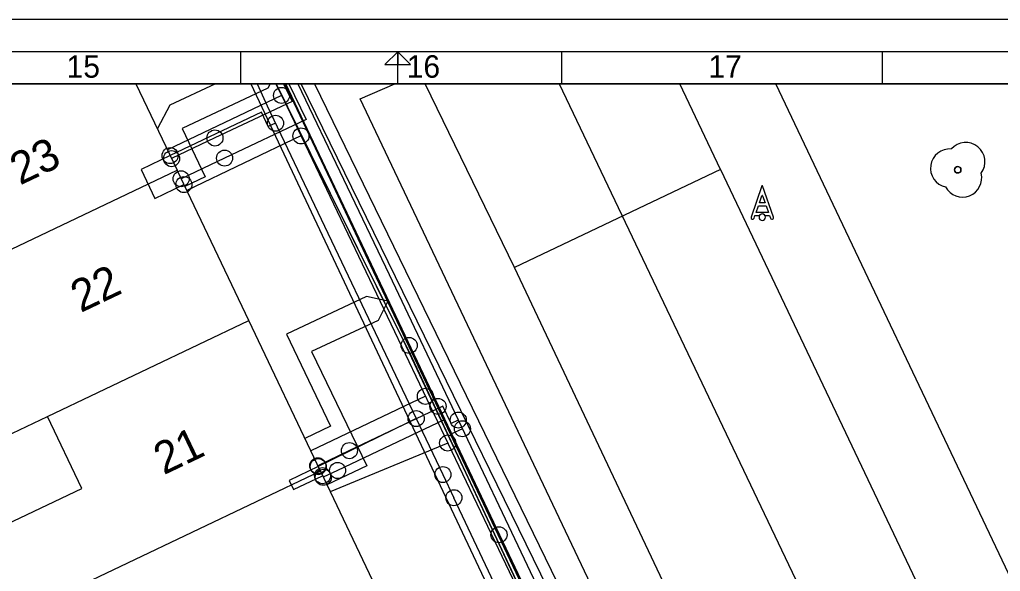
# Model space of a CAD drawing. Extents: x 192672 to 192910, y 446344 to 446512.
# Drawn here: x 192813.76 to 192844.33, y 446494.56 to 446511.76 of the extents above; entities that cross this region are included whole.
import ezdxf

# ---------------------------------------------------------------- set-up
doc = ezdxf.new("R2010")
doc.units = 0
for name, color, linetype in [('1010 viewport', 7, 'Continuous'), ('B-OI-KL-()_PUNTVANLEVERING_WATER-S', 7, 'Continuous'), ('B-OI-KL-BUISLEIDING_OLIEGASCHEMICALIEN_GASLAGEDRUK-G', 7, 'Continuous'), ('B-OI-KL-DATA-G', 7, 'Continuous'), ('B-OI-KL-DATA_KABELBED-G', 7, 'Continuous'), ('B-OI-KL-DATA_OVERIG-S', 7, 'Continuous'), ('B-OI-KL-ET_LS-G', 7, 'Continuous'), ('B-OI-KL-ET_LS_DELIVERYPOINT-S', 7, 'Continuous'), ('B-OI-KL-ET_LS_MOF-S', 7, 'Continuous'), ('B-OI-KL-GAS_LD_AFTAKZADEL-S', 7, 'Continuous'), ('B-OI-KL-GAS_LD_DELIVERYPOINT-S', 7, 'Continuous'), ('B-OI-KL-GAS_LD_OVERGANGSSTUK-S', 7, 'Continuous'), ('B-OI-KL-WATER-G', 7, 'Continuous'), ('B-OI-RI-RIOOLVRIJVERVAL-G', 7, 'Continuous'), ('boom', 7, 'Continuous'), ('bovenleidingmast', 7, 'Continuous'), ('Default', 7, 'Continuous'), ('huisnummerreeks BGT', 7, 'Continuous'), ('kant open verharding', 7, 'Continuous'), ('kant verharding', 7, 'Continuous'), ('pand op maaiveld vlak', 7, 'Continuous'), ('X-XX-AL-TEKENBLAD-S', 7, 'Continuous')]:
    doc.layers.add(name, color=color, linetype=linetype)

# ---------------------------------------------------------------- blocks, each defined once
blk = doc.blocks.new('B-OI-KL-GAS_LD_AFTAKZADEL-S')
at = {"layer": 'Default'}
blk.add_circle((0, 0), 0.25, dxfattribs=at)
blk = doc.blocks.new('B-OI-KL-GAS_LD_DELIVERYPOINT-S')
at = {"layer": 'Default'}
blk.add_circle((0, 0), 0.25, dxfattribs=at)
blk = doc.blocks.new('B-OI-KL-GAS_LD_OVERGANGSSTUK-S')
at = {"layer": 'Default'}
blk.add_circle((0, 0), 0.25, dxfattribs=at)
blk = doc.blocks.new('B-OI-KL-ET_LS_DELIVERYPOINT-S')
at = {"layer": 'Default'}
blk.add_circle((0, 0), 0.25, dxfattribs=at)
blk = doc.blocks.new('B-OI-KL-ET_LS_MOF-S')
at = {"layer": 'Default'}
blk.add_circle((0, 0), 0.25, dxfattribs=at)
blk = doc.blocks.new('B-OI-KL-DATA_OVERIG-S')
at = {"layer": 'Default'}
blk.add_circle((0, 0), 0.25, dxfattribs=at)
blk = doc.blocks.new('B-OI-KL-()_PUNTVANLEVERING_WATER-S')
at = {"layer": 'Default'}
blk.add_circle((0, 0), 0.25, dxfattribs=at)

msp = doc.modelspace()

# ---------------------------------------------------------------- linework, layer by layer
at = {"layer": '1010 viewport'}
msp.add_lwpolyline([(192675.743, 446509.756), (192860.643, 446509.756), (192860.643, 446345.556), (192675.743, 446345.556)], close=True, dxfattribs=at)
at = {"layer": 'B-OI-KL-BUISLEIDING_OLIEGASCHEMICALIEN_GASLAGEDRUK-G'}
for points in [[(192821.989, 446509.756), (192822.251, 446509.208), (192819.848, 446508.066)], [(192822.155, 446509.756), (192822.687, 446508.645), (192820.149, 446507.439)], [(192822.433, 446509.756), (192825.279, 446503.813), (192831.728, 446490.219), (192841.146, 446471.04), (192848.608, 446455.57), (192845.591, 446448.244), (192845.453, 446447.8)], [(192819.848, 446508.066), (192818.496, 446507.422)], [(192820.149, 446507.439), (192818.795, 446506.794)], [(192827.432, 446499.275), (192827.206, 446499.168), (192826.951, 446499.706), (192824.039, 446498.321)], [(192827.561, 446499.003), (192827.199, 446498.832), (192826.987, 446499.28), (192823.669, 446497.702)], [(192824.039, 446498.321), (192823.054, 446497.852)], [(192823.669, 446497.702), (192823.225, 446497.491)]]:
    msp.add_lwpolyline(points, dxfattribs=at)
at = {"layer": 'B-OI-KL-DATA-G'}
for q in [(192825.713, 446501.766), (192823.186, 446506.85)]:
    msp.add_line((192821.742, 446509.756), q, dxfattribs=at)
for points in [[(192819.864, 446509.756), (192818.447, 446509.084), (192818.053, 446508.359)], [(192821.572, 446509.756), (192821.501, 446509.616), (192818.831, 446508.364), (192819.548, 446506.856), (192818.913, 446506.553)], [(192821.742, 446509.756), (192825.984, 446501.22), (192835.895, 446480.007), (192842.472, 446466.378), (192848.635, 446454.503), (192848.764, 446454.232), (192845.185, 446446.654), (192842.489, 446440.231), (192836.203, 446423.068)], [(192821.742, 446509.756), (192825.984, 446501.22), (192835.895, 446480.007), (192842.472, 446466.378), (192848.635, 446454.503), (192848.764, 446454.232), (192845.185, 446446.654), (192842.489, 446440.231), (192836.203, 446423.068), (192839.811, 446421.866), (192851.515, 446418.004), (192854.977, 446417.712)], [(192821.742, 446509.756), (192825.984, 446501.22), (192835.895, 446480.007), (192842.472, 446466.378), (192842.564, 446466.201), (192838.77, 446464.389), (192838.682, 446464.573)], [(192821.742, 446509.756), (192825.984, 446501.22), (192835.895, 446480.007), (192838.867, 446473.848)], [(192821.742, 446509.756), (192825.984, 446501.22), (192835.895, 446480.007), (192836.607, 446478.531)], [(192821.742, 446509.756), (192825.984, 446501.22), (192834.713, 446482.538)], [(192821.742, 446509.756), (192825.984, 446501.22), (192832.292, 446487.72)], [(192821.742, 446509.756), (192825.984, 446501.22), (192830.072, 446492.472)], [(192821.742, 446509.756), (192825.984, 446501.22), (192828.007, 446496.891)], [(192821.742, 446509.756), (192825.984, 446501.22), (192835.895, 446480.007), (192842.472, 446466.378), (192848.635, 446454.503), (192848.764, 446454.232), (192845.185, 446446.654), (192842.489, 446440.231), (192836.203, 446423.068)], [(192821.742, 446509.756), (192825.984, 446501.22), (192835.895, 446480.007), (192842.472, 446466.378), (192848.635, 446454.503), (192848.764, 446454.232), (192845.185, 446446.654), (192842.489, 446440.231), (192836.203, 446423.068)], [(192821.742, 446509.756), (192825.984, 446501.22), (192835.895, 446480.007), (192842.472, 446466.378), (192848.635, 446454.503), (192848.764, 446454.232), (192845.185, 446446.654), (192842.489, 446440.231), (192836.203, 446423.068)], [(192821.742, 446509.756), (192825.984, 446501.22), (192835.895, 446480.007), (192842.472, 446466.378), (192848.635, 446454.503), (192848.764, 446454.232), (192845.185, 446446.654), (192842.489, 446440.231), (192836.203, 446423.068)], [(192821.742, 446509.756), (192825.984, 446501.22), (192835.895, 446480.007), (192842.472, 446466.378), (192848.635, 446454.503), (192848.764, 446454.232), (192845.185, 446446.654), (192842.489, 446440.231), (192836.203, 446423.068)], [(192821.742, 446509.756), (192825.984, 446501.22), (192835.895, 446480.007), (192842.472, 446466.378), (192848.635, 446454.503), (192848.764, 446454.232), (192845.185, 446446.654), (192842.489, 446440.231), (192836.203, 446423.068)], [(192821.742, 446509.756), (192825.984, 446501.22), (192835.895, 446480.007), (192842.472, 446466.378), (192848.635, 446454.503), (192848.764, 446454.232), (192845.185, 446446.654), (192842.489, 446440.231), (192836.203, 446423.068)], [(192822.031, 446509.756), (192825.241, 446502.984), (192833.914, 446484.678), (192835.489, 446481.354), (192838.315, 446478.134), (192842.706, 446469.973), (192847.716, 446462.173), (192853.316, 446454.787), (192859.471, 446447.855), (192860.643, 446453.004)], [(192822.031, 446509.756), (192825.241, 446502.984), (192833.914, 446484.678), (192835.489, 446481.354), (192838.315, 446478.134), (192842.706, 446469.973), (192847.716, 446462.173), (192853.316, 446454.787), (192859.471, 446447.855), (192860.643, 446453.004)], [(192822.031, 446509.756), (192825.241, 446502.984), (192833.914, 446484.678), (192835.489, 446481.354), (192838.315, 446478.134), (192842.706, 446469.973), (192847.716, 446462.173), (192853.316, 446454.787), (192859.471, 446447.855), (192860.643, 446453.004)], [(192860.643, 446452.955), (192859.5, 446447.9), (192838.3, 446478.1), (192835.5, 446481.4), (192830.8, 446491.2), (192824.7, 446504.1), (192822.051, 446509.756)], [(192860.643, 446452.955), (192859.5, 446447.9), (192838.3, 446478.1), (192835.5, 446481.4), (192822.054, 446509.756)], [(192860.643, 446452.955), (192859.5, 446447.9), (192838.3, 446478.1), (192835.5, 446481.4), (192822.054, 446509.756)], [(192825.241, 446502.984), (192824.576, 446503.125), (192822.076, 446501.955), (192823.452, 446499.079), (192822.65, 446498.697)], [(192825.241, 446502.984), (192824.932, 446502.378), (192822.852, 446501.411), (192824.585, 446497.846), (192823.339, 446497.253)]]:
    msp.add_lwpolyline(points, dxfattribs=at)
at = {"layer": 'B-OI-KL-DATA_KABELBED-G'}
msp.add_line((192821.761, 446509.756), (192823.186, 446506.85), dxfattribs=at)
for points in [[(192823.186, 446506.85), (192825.713, 446501.766)], [(192825.713, 446501.766), (192828.007, 446496.891)], [(192828.007, 446496.891), (192830.072, 446492.472)]]:
    msp.add_lwpolyline(points, dxfattribs=at)
at = {"layer": 'B-OI-KL-ET_LS-G'}
for points in [[(192821.164, 446509.756), (192821.478, 446509.066), (192826.951, 446497.576)], [(192835.58, 446487.244), (192835.284, 446487.252), (192833.85, 446486.608), (192822.538, 446509.756)], [(192822.952, 446509.756), (192850.947, 446452.216), (192860.643, 446456.683)], [(192821.735, 446508.527), (192821.509, 446508.419), (192821.294, 446508.871), (192818.451, 446507.516)], [(192818.451, 446507.516), (192817.548, 446507.087), (192817.978, 446506.183), (192818.881, 446506.613)], [(192826.119, 446499.321), (192825.894, 446499.213), (192823.068, 446497.822)], [(192823.068, 446497.822), (192822.165, 446497.392), (192822.299, 446497.111), (192823.202, 446497.541)], [(192826.951, 446497.576), (192827.295, 446496.854)], [(192842.476, 446464.719), (192841.84, 446466.076), (192827.295, 446496.854)]]:
    msp.add_lwpolyline(points, dxfattribs=at)
at = {"layer": 'B-OI-KL-WATER-G'}
msp.add_line((192821.752, 446509.756), (192849.771, 446451.113), dxfattribs=at)
for points in [[(192821.925, 446509.393), (192818.365, 446507.697)], [(192822.529, 446508.129), (192818.967, 446506.433)], [(192826.406, 446500.014), (192822.834, 446498.312)], [(192827.101, 446498.559), (192823.44, 446497.04)]]:
    msp.add_lwpolyline(points, dxfattribs=at)
at = {"layer": 'B-OI-RI-RIOOLVRIJVERVAL-G'}
msp.add_line((192830.572, 446509.756), (192838.8, 446492.53), dxfattribs=at)
at = {"layer": 'boom'}
msp.add_circle((192842.997, 446507.076), 0.1, dxfattribs=at)
for centre, radius, start, end in [((192843.247, 446507.326), 0.6, 323.5446, 138.4658), ((192842.747, 446507.126), 0.6, 85.137, 257.7544), ((192843.147, 446506.826), 0.6, 208.5058, 13.8356), ((192842.997, 446507.076), 0.1, 0, 180), ((192842.997, 446507.076), 0.1, 180, 0)]:
    msp.add_arc(centre, radius, start, end, dxfattribs=at)
at = {"layer": 'bovenleidingmast'}
for p, q in [((192836.896, 446506.571), (192836.555, 446505.598)), ((192837.255, 446505.598), (192836.914, 446506.571))]:
    msp.add_line(p, q, dxfattribs=at)
for points in [[(192836.914, 446506.268), (192836.992, 446506.048), (192836.818, 446506.048), (192836.896, 446506.268)], [(192836.649, 446505.565), (192836.678, 446505.648), (192836.818, 446505.648)], [(192836.992, 446505.648), (192837.132, 446505.648), (192837.161, 446505.565)]]:
    msp.add_lwpolyline(points, dxfattribs=at)
msp.add_lwpolyline([(192837.027, 446505.948), (192837.097, 446505.748), (192836.713, 446505.748), (192836.783, 446505.948)], close=True, dxfattribs=at)
for centre, radius, start, end in [((192836.905, 446506.568), 0.01, 19.29, 160.71), ((192836.905, 446506.265), 0.01, 19.29, 160.71), ((192836.905, 446505.598), 0.1, 0, 180), ((192836.905, 446505.598), 0.1, 30, 150), ((192836.602, 446505.581), 0.05, 160.71, 340.71), ((192836.905, 446505.598), 0.1, 180, 0), ((192837.208, 446505.581), 0.05, 199.29, 19.29)]:
    msp.add_arc(centre, radius, start, end, dxfattribs=at)
at = {"layer": 'kant open verharding'}
for p, q in [((192849.384, 446484.404), (192837.327, 446509.756)), ((192835.606, 446507.086), (192829.185, 446504.028)), ((192835.606, 446507.086), (192852.92, 446470.626))]:
    msp.add_line(p, q, dxfattribs=at)
msp.add_lwpolyline([(192820.967, 446509.756), (192830.801, 446488.882), (192835.291, 446479.169), (192839.711, 446469.931), (192846.946, 446454.816)], dxfattribs=at)
at = {"layer": 'kant verharding'}
for p, q in [((192829.185, 446504.028), (192826.401, 446509.756)), ((192835.606, 446507.086), (192834.338, 446509.756)), ((192847.908, 446464.417), (192829.185, 446504.028))]:
    msp.add_line(p, q, dxfattribs=at)
msp.add_lwpolyline([(192847.34, 446464.645), (192845.844, 446464.076), (192824.376, 446509.29), (192825.458, 446509.756)], dxfattribs=at)
at = {"layer": 'pand op maaiveld vlak'}
for p, q in [((192817.385, 446509.756), (192818.666, 446507.065)), ((192809.329, 446502.618), (192818.666, 446507.065)), ((192820.9, 446502.373), (192818.666, 446507.065)), ((192814.631, 446499.387), (192820.9, 446502.373)), ((192823.135, 446497.681), (192820.9, 446502.373)), ((192823.135, 446497.681), (192813.859, 446493.264)), ((192823.135, 446497.681), (192825.369, 446492.989))]:
    msp.add_line(p, q, dxfattribs=at)
for points in [[(192809.329, 446502.618), (192810.506, 446500.147), (192810.302, 446500.05), (192811.352, 446497.825), (192814.631, 446499.387)], [(192813.859, 446493.264), (192812.693, 446495.713), (192815.699, 446497.145), (192814.631, 446499.387)]]:
    msp.add_lwpolyline(points, dxfattribs=at)
at = {"layer": 'X-XX-AL-TEKENBLAD-S'}
for p, q in [((192909.543, 446511.756), (192671.743, 446511.756)), ((192908.543, 446510.756), (192674.743, 446510.756)), ((192820.643, 446510.756), (192820.643, 446509.756)), ((192825.543, 446509.756), (192825.543, 446510.756)), ((192830.643, 446510.756), (192830.643, 446509.756)), ((192840.643, 446510.756), (192840.643, 446509.756))]:
    msp.add_line(p, q, dxfattribs=at)
for points in [[(192825.543, 446510.356), (192825.543, 446510.756), (192825.143, 446510.356), (192825.543, 446510.356)], [(192825.543, 446510.756), (192825.543, 446510.356), (192825.943, 446510.356), (192825.543, 446510.756)]]:
    msp.add_lwpolyline(points, dxfattribs=at)
msp.add_lwpolyline([(192675.743, 446345.556), (192907.543, 446345.556), (192907.543, 446509.756), (192675.743, 446509.756)], close=True, dxfattribs=at)

# ---------------------------------------------------------------- block references
at = {"layer": 'B-OI-KL-()_PUNTVANLEVERING_WATER-S'}
for p in [(192821.925, 446509.393), (192822.529, 446508.129), (192826.406, 446500.014), (192827.101, 446498.559)]:
    msp.add_blockref('B-OI-KL-()_PUNTVANLEVERING_WATER-S', p, dxfattribs=at)
at = {"layer": 'B-OI-KL-DATA_OVERIG-S'}
for p in [(192825.9, 446501.6), (192826.8, 446499.7), (192828.7, 446495.7)]:
    msp.add_blockref('B-OI-KL-DATA_OVERIG-S', p, dxfattribs=at)
at = {"layer": 'B-OI-KL-ET_LS_DELIVERYPOINT-S'}
for p in [(192818.451, 446507.516), (192818.881, 446506.613), (192823.068, 446497.822), (192823.202, 446497.541)]:
    msp.add_blockref('B-OI-KL-ET_LS_DELIVERYPOINT-S', p, dxfattribs=at)
at = {"layer": 'B-OI-KL-ET_LS_MOF-S'}
for p in [(192821.735, 446508.527), (192826.119, 446499.321), (192826.951, 446497.576), (192827.295, 446496.854)]:
    msp.add_blockref('B-OI-KL-ET_LS_MOF-S', p, dxfattribs=at)
at = {"layer": 'B-OI-KL-GAS_LD_AFTAKZADEL-S'}
for p in [(192827.432, 446499.275), (192827.561, 446499.003)]:
    msp.add_blockref('B-OI-KL-GAS_LD_AFTAKZADEL-S', p, dxfattribs=at)
at = {"layer": 'B-OI-KL-GAS_LD_DELIVERYPOINT-S'}
for p in [(192818.496, 446507.422), (192818.795, 446506.794), (192823.054, 446497.852), (192823.225, 446497.491)]:
    msp.add_blockref('B-OI-KL-GAS_LD_DELIVERYPOINT-S', p, dxfattribs=at)
at = {"layer": 'B-OI-KL-GAS_LD_OVERGANGSSTUK-S'}
for p in [(192819.848, 446508.066), (192820.149, 446507.439), (192824.039, 446498.321), (192823.669, 446497.702)]:
    msp.add_blockref('B-OI-KL-GAS_LD_OVERGANGSSTUK-S', p, dxfattribs=at)

# ---------------------------------------------------------------- texts
at = {"layer": 'huisnummerreeks BGT'}
for s, p in [('23', (192813.772, 446506.583)), ('22', (192815.664, 446502.609)), ('21', (192818.252, 446497.553))]:
    msp.add_text(s, height=1, rotation=25.5, dxfattribs=at).set_placement(p)
at = {"layer": 'X-XX-AL-TEKENBLAD-S'}
for s, p in [('15', (192815.224, 446509.945)), ('16', (192825.824, 446509.945)), ('17', (192835.224, 446509.945))]:
    msp.add_text(s, height=0.7, dxfattribs=at).set_placement(p)

doc.saveas('drawing.dxf')
